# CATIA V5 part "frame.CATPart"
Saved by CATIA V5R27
Part number: frame
Source: Unknown
Bounding box of the stored display mesh (mm): x -200 to 0, y -58 to 52, z 8 to 78
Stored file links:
  H:\STEP-Test-cases\public\installation-with-fasteners\tc4-assembly-PAG\STEP\frame.CATPart
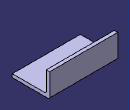
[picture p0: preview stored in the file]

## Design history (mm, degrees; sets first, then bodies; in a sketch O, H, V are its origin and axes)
AxisSystem1: origin (0, 0, 0), X (1, 0, 0), Y (0, 1, 0), Z (0, 0, 1)
Body1 (main body)
  Solid1 "PartBody": solid without history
